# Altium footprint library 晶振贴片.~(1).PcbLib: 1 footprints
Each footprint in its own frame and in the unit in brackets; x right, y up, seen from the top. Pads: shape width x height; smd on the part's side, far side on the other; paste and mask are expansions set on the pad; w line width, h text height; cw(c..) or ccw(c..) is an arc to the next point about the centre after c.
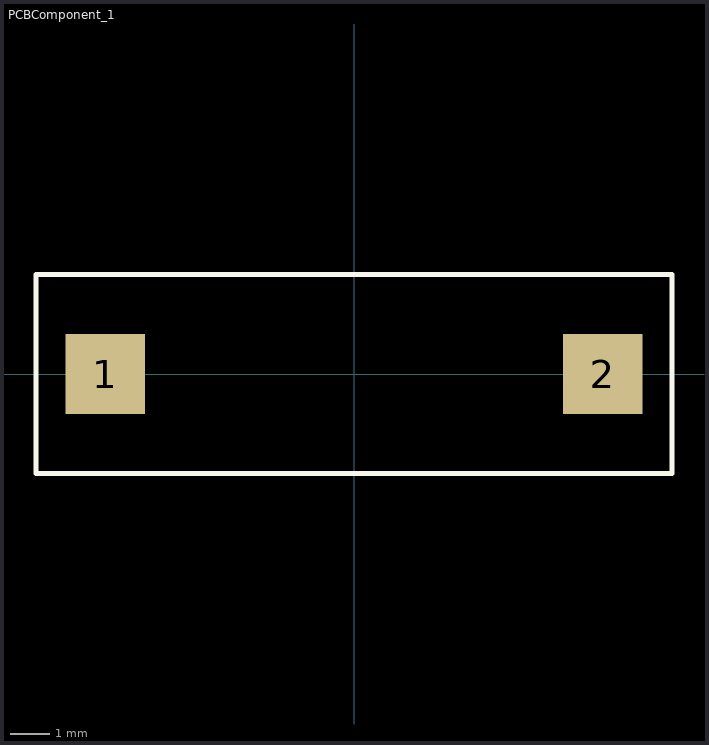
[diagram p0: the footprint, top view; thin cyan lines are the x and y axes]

## PCBComponent_1 [mm]
pads (2):
  rect 2x2 smd: 1(-6.25,0) 2(6.25,0)
Top Overlay:
  lines w0.127: 0,2.5 -7.5,2.5 ; -7.5,2.5 8,2.5 8,-2.5 -8,-2.5 -8,2 -8,2.5 -7.5,2.5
